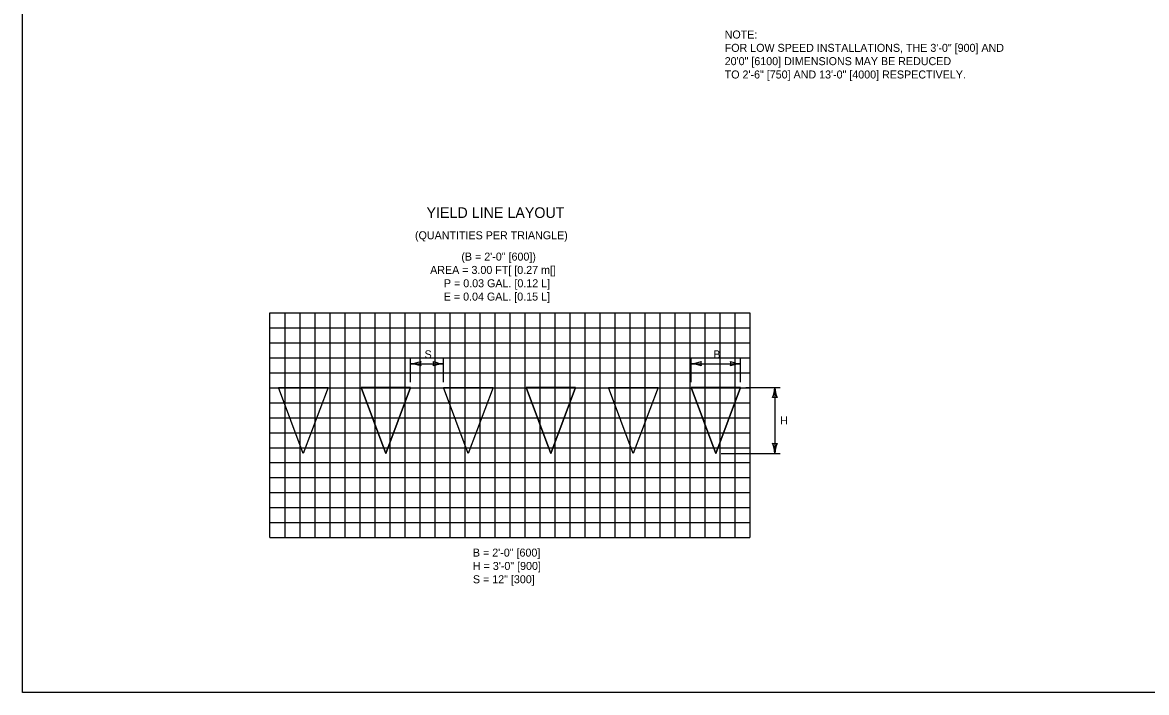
# Model space of a CAD drawing. Extents: x 49948.7 to 50021, y 49977 to 50017.6.
# Drawn here: x 49999.38 to 50007.81, y 49987.8 to 49992.83 of the extents above; entities that cross this region are included whole.
import ezdxf

# ---------------------------------------------------------------- set-up
doc = ezdxf.new("R2010")
doc.units = 0
for name, color, linetype in [('Level 1', 7, 'Continuous'), ('Level 2', 7, 'Continuous'), ('Level 3', 7, 'Continuous'), ('Level 9', 7, 'Continuous')]:
    doc.layers.add(name, color=color, linetype=linetype)

msp = doc.modelspace()

# ---------------------------------------------------------------- linework, layer by layer
at = {"layer": 'Level 1'}
for p, q in [((50001.3035, 49990.0877), (50001.6748, 49990.0877)), ((50001.4892, 49989.5927), (50001.3035, 49990.0877)), ((50001.4892, 49989.5927), (50001.3035, 49990.0877)), ((50001.3035, 49990.0877), (50001.6748, 49990.0877)), ((50001.4892, 49989.5927), (50001.3035, 49990.0877)), ((50001.3035, 49990.0877), (50001.6748, 49990.0877)), ((50001.6748, 49990.0877), (50001.4892, 49989.5927)), ((50001.6748, 49990.0877), (50001.4892, 49989.5927)), ((50001.6748, 49990.0877), (50001.4892, 49989.5927)), ((50002.2935, 49990.0877), (50001.9223, 49990.0877)), ((50001.9223, 49990.0877), (50002.1079, 49989.5927)), ((50002.1079, 49989.5927), (50001.9223, 49990.0877)), ((50001.9223, 49990.0877), (50002.2935, 49990.0877)), ((50002.1079, 49989.5927), (50001.9223, 49990.0877)), ((50001.9223, 49990.0877), (50002.2935, 49990.0877)), ((50002.1079, 49989.5927), (50002.2935, 49990.0877)), ((50002.2935, 49990.0877), (50002.1079, 49989.5927)), ((50002.2935, 49990.0877), (50002.1079, 49989.5927)), ((50002.541, 49990.0877), (50002.9123, 49990.0877)), ((50002.7267, 49989.5927), (50002.541, 49990.0877)), ((50002.7267, 49989.5927), (50002.541, 49990.0877)), ((50002.541, 49990.0877), (50002.9123, 49990.0877)), ((50002.7267, 49989.5927), (50002.541, 49990.0877)), ((50002.541, 49990.0877), (50002.9123, 49990.0877)), ((50002.9123, 49990.0877), (50002.7267, 49989.5927)), ((50002.9123, 49990.0877), (50002.7267, 49989.5927)), ((50002.9123, 49990.0877), (50002.7267, 49989.5927)), ((50003.531, 49990.0877), (50003.1598, 49990.0877)), ((50003.1598, 49990.0877), (50003.3454, 49989.5927)), ((50003.3454, 49989.5927), (50003.1598, 49990.0877)), ((50003.1598, 49990.0877), (50003.531, 49990.0877)), ((50003.3454, 49989.5927), (50003.1598, 49990.0877)), ((50003.1598, 49990.0877), (50003.531, 49990.0877)), ((50003.3454, 49989.5927), (50003.531, 49990.0877)), ((50003.531, 49990.0877), (50003.3454, 49989.5927)), ((50003.531, 49990.0877), (50003.3454, 49989.5927)), ((50003.7785, 49990.0877), (50004.1498, 49990.0877)), ((50003.9642, 49989.5927), (50003.7785, 49990.0877)), ((50003.9642, 49989.5927), (50003.7785, 49990.0877)), ((50003.7785, 49990.0877), (50004.1498, 49990.0877)), ((50003.7785, 49990.0877), (50004.1498, 49990.0877)), ((50003.9642, 49989.5927), (50003.7785, 49990.0877)), ((50004.1498, 49990.0877), (50003.9642, 49989.5927)), ((50004.1498, 49990.0877), (50003.9642, 49989.5927)), ((50004.1498, 49990.0877), (50003.9642, 49989.5927)), ((50004.7685, 49990.0877), (50004.3973, 49990.0877)), ((50004.3973, 49990.0877), (50004.5829, 49989.5927)), ((50004.5829, 49989.5927), (50004.3973, 49990.0877)), ((50004.3973, 49990.0877), (50004.7685, 49990.0877)), ((50004.5829, 49989.5927), (50004.3973, 49990.0877)), ((50004.3973, 49990.0877), (50004.7685, 49990.0877)), ((50004.5829, 49989.5927), (50004.7685, 49990.0877)), ((50004.7685, 49990.0877), (50004.5829, 49989.5927)), ((50004.7685, 49990.0877), (50004.5829, 49989.5927))]:
    msp.add_line(p, q, dxfattribs=at)
msp.add_lwpolyline([(49999.3835, 49998.9992), (50016.7501, 49998.9992), (50016.7501, 49987.7988), (49999.3835, 49987.7988)], close=True, dxfattribs=at)
at = {"layer": 'Level 3'}
for p, q in [((50002.2935, 49990.1277), (50002.2935, 49990.3065)), ((50002.2935, 49990.2665), (50002.541, 49990.2665)), ((50002.541, 49990.1277), (50002.541, 49990.3065)), ((50004.3973, 49990.1277), (50004.3973, 49990.3065)), ((50004.3973, 49990.2665), (50004.7685, 49990.2665)), ((50004.7685, 49990.1277), (50004.7685, 49990.3065)), ((50004.8085, 49990.0877), (50005.0655, 49990.0877)), ((50005.0255, 49990.0877), (50005.0255, 49989.5927)), ((50004.6229, 49989.5927), (50005.0655, 49989.5927))]:
    msp.add_line(p, q, dxfattribs=at)
for centre, radius, start, end in [((50002.282, 49990.4992), 0.233, 272.82731, 292.07716), ((50002.2844, 49990.0444), 0.2223, 67.45601, 87.63952), ((50002.4218, 49990.2665), 0.0548, 162.13882, 197.86118), ((50002.5502, 49990.4886), 0.2223, 247.45601, 267.63952), ((50002.4128, 49990.2665), 0.0548, 342.13882, 17.86118), ((50002.5525, 49990.0338), 0.233, 92.82731, 112.07716), ((50004.3858, 49990.4992), 0.233, 272.82731, 292.07716), ((50004.3881, 49990.0444), 0.2223, 67.45601, 87.63952), ((50004.5255, 49990.2665), 0.0548, 162.13882, 197.86118), ((50004.7777, 49990.4886), 0.2223, 247.45601, 267.63952), ((50004.6403, 49990.2665), 0.0548, 342.13882, 17.86118), ((50004.78, 49990.0338), 0.233, 92.82731, 112.07716), ((50004.8034, 49990.0968), 0.2223, 337.45601, 357.63952), ((50005.2583, 49990.0992), 0.233, 182.82731, 202.07716), ((50005.0255, 49989.9595), 0.0548, 72.13882, 107.86118), ((50005.0255, 49989.7209), 0.0548, 252.13882, 287.86118), ((50004.7928, 49989.5812), 0.233, 2.82731, 22.07716), ((50005.2477, 49989.5835), 0.2223, 157.45601, 177.63952)]:
    msp.add_arc(centre, radius, start, end, dxfattribs=at)
at = {"layer": 'Level 9'}
for p, q in [((50001.2389, 49988.9612), (50001.2389, 49990.6487)), ((50001.2389, 49990.6487), (50004.8389, 49990.6487)), ((50001.3514, 49990.6487), (50001.3514, 49988.9612)), ((50001.4639, 49990.6487), (50001.4639, 49988.9612)), ((50001.5764, 49990.6487), (50001.5764, 49988.9612)), ((50001.6889, 49990.6487), (50001.6889, 49988.9612)), ((50001.8014, 49990.6487), (50001.8014, 49988.9612)), ((50001.9139, 49990.6487), (50001.9139, 49988.9612)), ((50002.0264, 49990.6487), (50002.0264, 49988.9612)), ((50002.1389, 49990.6487), (50002.1389, 49988.9612)), ((50002.2514, 49990.6487), (50002.2514, 49988.9612)), ((50002.3639, 49990.6487), (50002.3639, 49988.9612)), ((50002.4764, 49990.6487), (50002.4764, 49988.9612)), ((50002.5889, 49990.6487), (50002.5889, 49988.9612)), ((50002.7014, 49990.6487), (50002.7014, 49988.9612)), ((50002.8139, 49990.6487), (50002.8139, 49988.9612)), ((50002.9264, 49990.6487), (50002.9264, 49988.9612)), ((50003.0389, 49990.6487), (50003.0389, 49988.9612)), ((50003.1514, 49990.6487), (50003.1514, 49988.9612)), ((50003.2639, 49990.6487), (50003.2639, 49988.9612)), ((50003.3764, 49990.6487), (50003.3764, 49988.9612)), ((50003.4889, 49990.6487), (50003.4889, 49988.9612)), ((50003.6014, 49990.6487), (50003.6014, 49988.9612)), ((50003.7139, 49990.6487), (50003.7139, 49988.9612)), ((50003.8264, 49990.6487), (50003.8264, 49988.9612)), ((50003.9389, 49990.6487), (50003.9389, 49988.9612)), ((50004.0514, 49990.6487), (50004.0514, 49988.9612)), ((50004.1639, 49990.6487), (50004.1639, 49988.9612)), ((50004.2764, 49990.6487), (50004.2764, 49988.9612)), ((50004.3889, 49990.6487), (50004.3889, 49988.9612)), ((50004.5014, 49990.6487), (50004.5014, 49988.9612)), ((50004.6139, 49990.6487), (50004.6139, 49988.9612)), ((50004.7264, 49990.6487), (50004.7264, 49988.9612)), ((50004.8389, 49990.6487), (50004.8389, 49988.9612)), ((50001.2389, 49990.5362), (50004.8389, 49990.5362)), ((50001.2389, 49990.4237), (50004.8389, 49990.4237)), ((50001.2389, 49990.3112), (50004.8389, 49990.3112)), ((50001.2389, 49990.1987), (50004.8389, 49990.1987)), ((50001.2389, 49990.0862), (50004.8389, 49990.0862)), ((50001.2389, 49989.9737), (50004.8389, 49989.9737)), ((50001.2389, 49989.8612), (50004.8389, 49989.8612)), ((50001.2389, 49989.7487), (50004.8389, 49989.7487)), ((50001.2389, 49989.6362), (50004.8389, 49989.6362)), ((50001.2389, 49989.5237), (50004.8389, 49989.5237)), ((50001.2389, 49989.4112), (50004.8389, 49989.4112)), ((50001.2389, 49989.2987), (50004.8389, 49989.2987)), ((50001.2389, 49989.1862), (50004.8389, 49989.1862)), ((50001.2389, 49989.0737), (50004.8389, 49989.0737)), ((50001.2389, 49988.9612), (50004.8389, 49988.9612))]:
    msp.add_line(p, q, dxfattribs=at)

# ---------------------------------------------------------------- texts
at = {"layer": 'Level 2'}
for s, height, p in [('NOTE:  ', 0.06, (50004.6494, 49992.7065)), ('FOR LOW SPEED INSTALLATIONS, THE 3\'-0" [900] AND ', 0.06, (50004.6494, 49992.6065)), ('20\'0" [6100] DIMENSIONS MAY BE REDUCED', 0.06, (50004.6494, 49992.5065)), ('TO 2\'-6" [750] AND 13\'-0" [4000] RESPECTIVELY.', 0.06, (50004.6494, 49992.4065)), ('YIELD LINE LAYOUT', 0.08, (50002.4134, 49991.3599)), ('(QUANTITIES PER TRIANGLE)', 0.06, (50002.327, 49991.1999)), ('(B = 2\'-0" [600])', 0.06, (50002.6748, 49991.0399)), ('AREA = 3.00 FT[ [0.27 m[]', 0.06, (50002.4407, 49990.9399)), ('P = 0.03 GAL. [0.12 L]', 0.06, (50002.5441, 49990.8399)), ('E = 0.04 GAL. [0.15 L]', 0.06, (50002.543, 49990.7399)), ('S', 0.06, (50002.3989, 49990.3065)), ('B', 0.06, (50004.5643, 49990.3065)), ('H', 0.06, (50005.0655, 49989.8102)), ('B = 2\'-0" [600]', 0.06, (50002.7614, 49988.8187)), ('H = 3\'-0" [900] ', 0.06, (50002.7614, 49988.7187)), ('S = 12" [300]', 0.06, (50002.7614, 49988.6187))]:
    msp.add_text(s, height=height, dxfattribs=at).set_placement(p)

doc.saveas('drawing.dxf')
